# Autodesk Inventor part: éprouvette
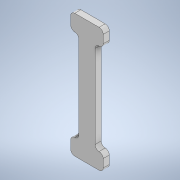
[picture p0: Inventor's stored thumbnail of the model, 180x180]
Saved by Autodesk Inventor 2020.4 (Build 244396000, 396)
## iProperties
Created: 2021-06
Part Number: éprouvette
Material: Générique
Document SubType Name: Modeling
Designer: mel
Density: 1 g/cm^3
Appearance: Par défaut
Author: mel
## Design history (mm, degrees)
sketch "Esquisse1"
  geometry: L1 (2, 0)-(14, 0); L2 (14, 61)-(2, 61); L3 (2, 53)-(2, 53); L4 (4, 51)-(4, 10); L5 (2, 8)-(2, 8); L6 (14, 53)-(14, 53); L7 (12, 51)-(12, 10); L8 (14, 8)-(14, 8); L9 (0, 59)-(0, 55); L10 (0, 6)-(0, 2); L11 (16, 2)-(16, 6); L12 (16, 55)-(16, 59); A1 r 2 centre (2, 59) between (2, 61) and (0, 59); A2 r 2 centre (2, 55) between (0, 55) and (2, 53); A3 r 2 centre (2, 51) between (4, 51) and (2, 53); A4 r 2 centre (14, 59) between (16, 59) and (14, 61); A5 r 2 centre (14, 55) between (14, 53) and (16, 55); A6 r 2 centre (14, 51) between (14, 53) and (12, 51); A7 r 2 centre (2, 10) between (2, 8) and (4, 10); A8 r 2 centre (2, 6) between (2, 8) and (0, 6); A9 r 2 centre (2, 2) between (0, 2) and (2, 0); A10 r 2 centre (14, 2) between (14, 0) and (16, 2); A11 r 2 centre (14, 6) between (16, 6) and (14, 8); A12 r 2 centre (14, 10) between (12, 10) and (14, 8); 7 further points
  constraints: 24 end point, 24 point on circle, 24 tangent, 12 centre point, 11 equal radius, 8 point on line, 7 parallel, 4 perpendicular, 3 horizontal
  dimensions: "d1" = 61 distance between parallel lines of L1 L2; "d2" = 16 distance between parallel lines of L12 L9; "d3" = 16 distance between parallel lines of L11 L10; "d4" = 8 distance between parallel lines of L5 L1; "d5" = 8 distance between parallel lines of L1 L8 (derived); "d6" = 8 distance between parallel lines of L2 L3 (= d4); "d7" = 8 distance between parallel lines of L2 L6 (derived); "d8" = 8 distance between parallel lines of L7 L4 (= d6); "d9" = 4 distance between parallel lines of L4 L9 (= -0.5 x d8 + 0.5 x d2); "d10" = 4 distance between parallel lines of L12 L7 (derived); "d11" = 2 radius of A1 (derived)
extrude "Extrusion1" new body sketch "Esquisse1" distance "d12" = 3; taper "d13" = 0 deg
node "Solide1"
other parameters: "d0" = 16
